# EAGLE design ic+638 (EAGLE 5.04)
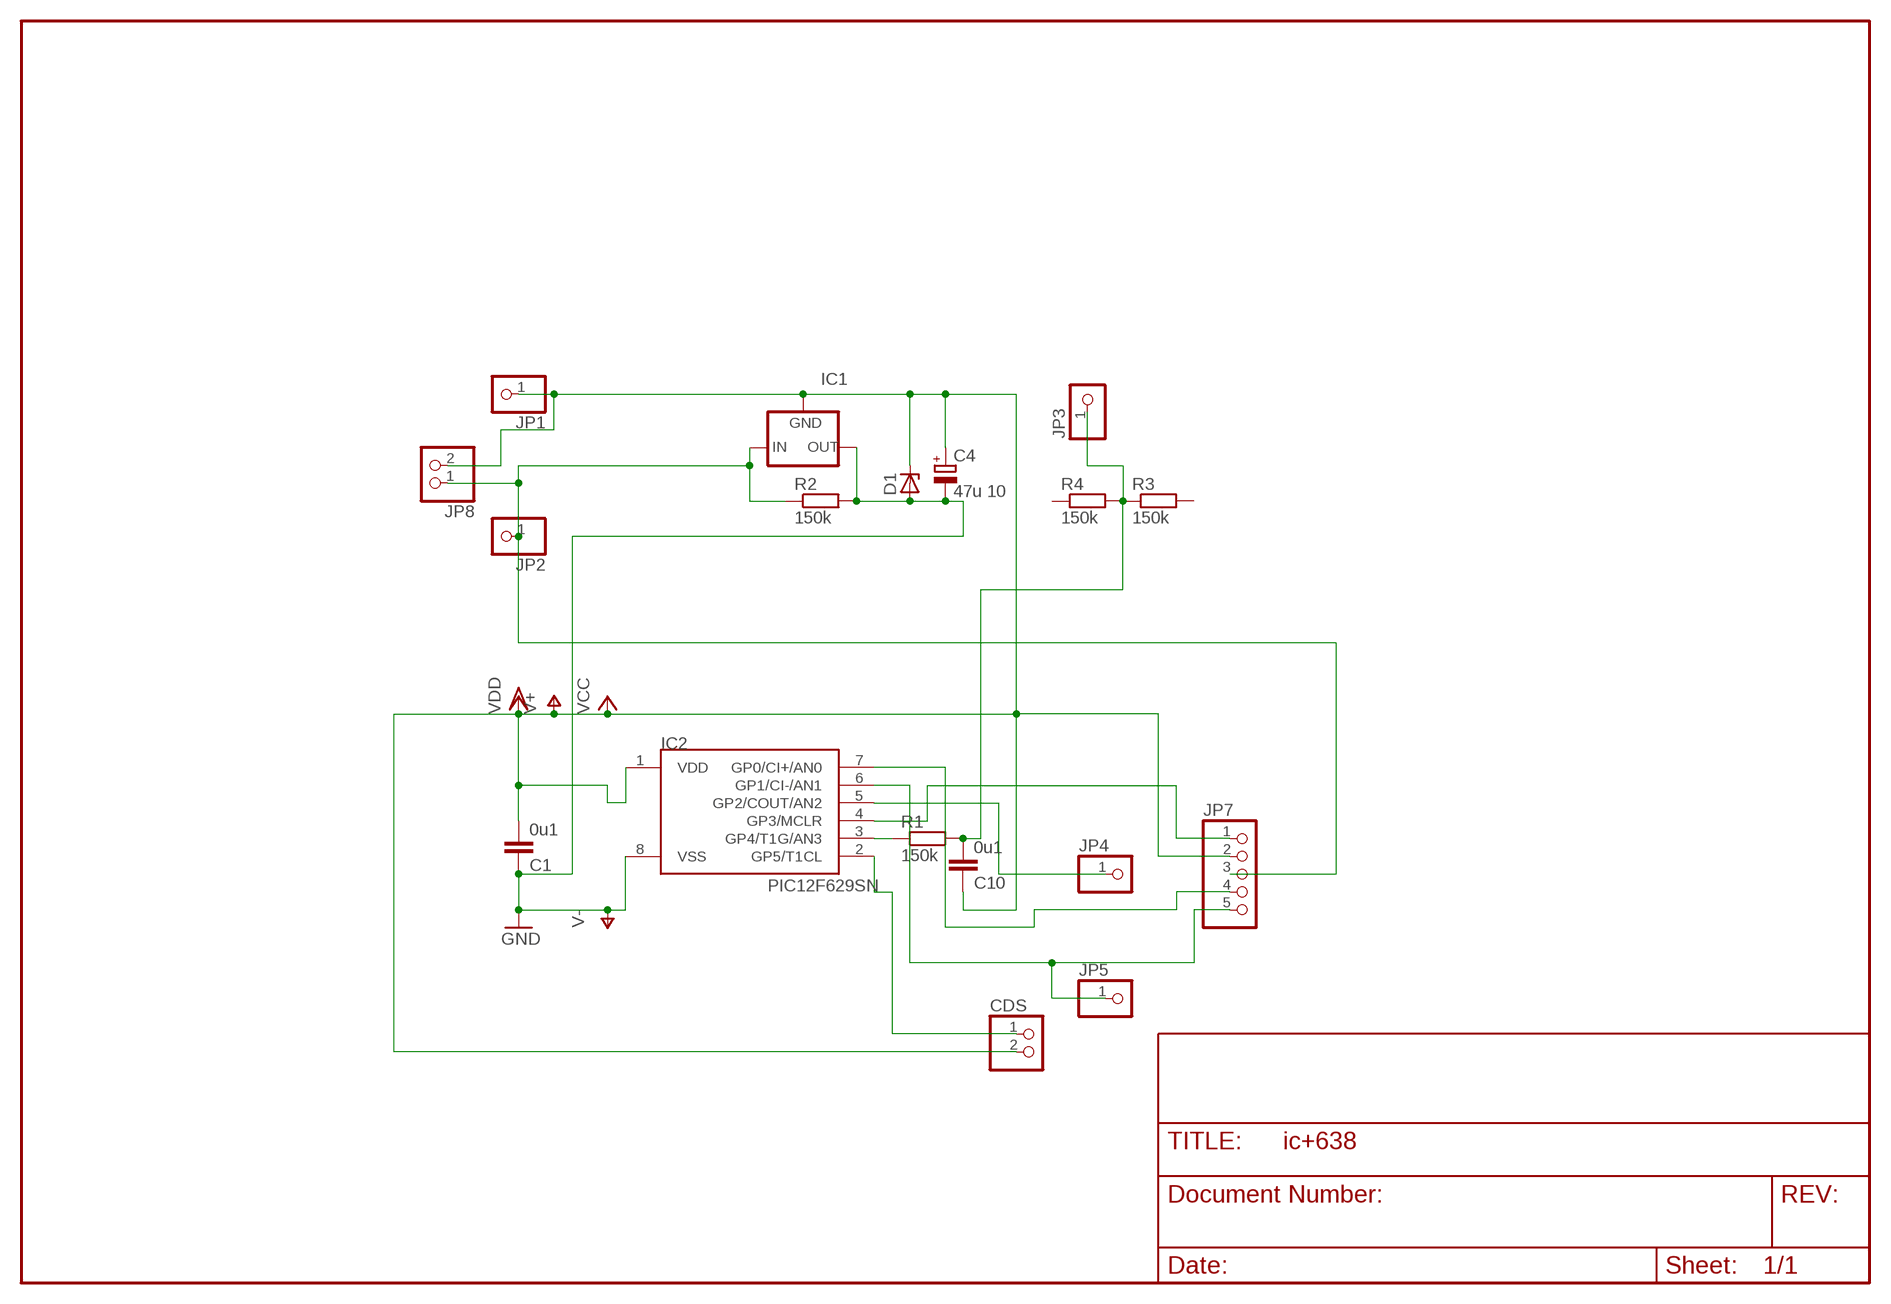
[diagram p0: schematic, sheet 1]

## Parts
C1  0u1  C-EUC1206  [C1206]
C4  47u 10  CPOL-EUE2.5-6  [E2,5-6]
C10  0u1  C-EUC1206  [C1206]
CDS  PINHD-1X2  [1X02]
D1  ZENER-DIODESOT23  [SOT23]
IC1  79LXX  [79LXX]
IC2  PIC12F629SN  [SO-08]
JP1  PINHD-1X1  [1X01]
JP2  PINHD-1X1  [1X01]
JP3  PINHD-1X1  [1X01]
JP4  PINHD-1X1  [1X01]
JP5  PINHD-1X1  [1X01]
JP7  PINHD-1X5  [1X05]
JP8  PINHD-1X2  [1X02]
R1  150k  R-EU_0204/2V  [0204V]
R2  150k  R-EU_0204/2V  [0204V]
R3  150k  R-EU_0204/2V  [0204V]
R4  150k  R-EU_0204/2V  [0204V]

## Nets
CDS: CDS.1 IC2.2(GP5/T1CL)
N$1: C10.2 JP3.1 R1.2 R3.1 R4.2
N$2: IC2.5(GP2/COUT/AN2) JP4.1
N$3: IC2.4(GP3/MCLR) JP7.1
N$8: IC2.3(GP4/T1G/AN3) R1.1
N$9: IC2.7(GP0/CI+/AN0) JP7.4
N$10: IC1.IN JP2.1 JP7.3 JP8.1 R2.1
N$15: IC2.6(GP1/CI-/AN1) JP5.1 JP7.5
V+: C1.2 C4.+ C10.1 CDS.2 D1.3(C) IC1.GND IC2.1(VDD) JP1.1 JP7.2 JP8.2 ; supply symbol labelled VCC, VDD
V-: C1.1 C4.- D1.1(A) IC1.OUT IC2.8(VSS) R2.2 ; supply symbol labelled GND
Unconnected: R3.2 R4.1

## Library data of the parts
C1 C10 = rcl:C-EU: CAPACITOR, European symbol
C4 = rcl:CPOL-EU: POLARIZED CAPACITOR, European symbol
CDS JP8 = pinhead:PINHD-1X2: PIN HEADER
D1 = diode-1:ZENER-DIODE: Z-Diode
IC1 = v-reg:79LXX: VOLTAGE REGULATOR
IC2 = microchip-3:PIC12F6*: uPC nW 1k Program Flash memory 2x Timer Comparator 10b A/D converter/ 4xIN
JP1-JP5 = pinhead:PINHD-1X1: PIN HEADER
JP7 = pinhead:PINHD-1X5: PIN HEADER
R1-R4 = rcl:R-EU_: RESISTOR, European symbol

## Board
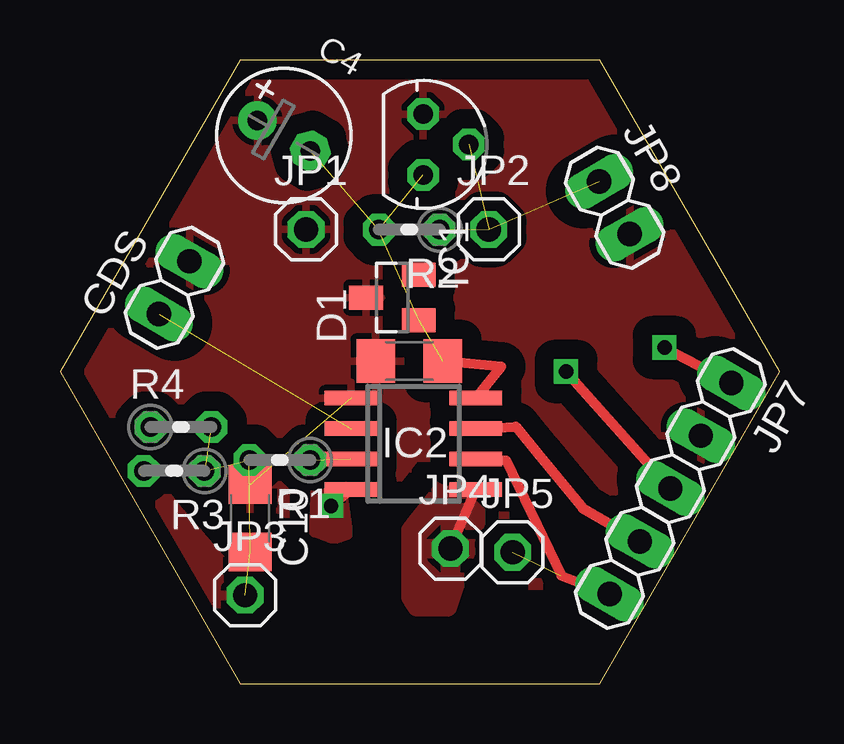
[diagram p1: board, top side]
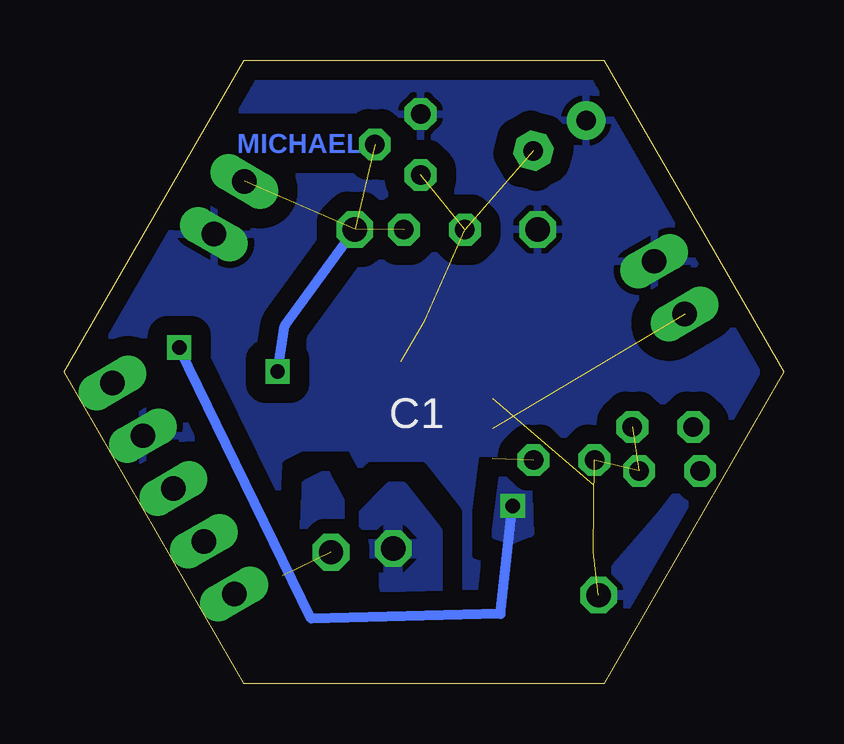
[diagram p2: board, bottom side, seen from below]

Size 30 x 25.98 mm. Coordinates in mm from the lower left corner, seen from the top.
Outline: 7.5,0 22.5,0 30,12.99 22.5,25.98 7.5,25.98 0,12.99 7.5,0
Copper layers (1*16): Top 0.035mm / dielectric 1.5mm / Bottom 0.035mm
Design rules "default *": minimum track width 10mil, minimum drill 24mil, track to track 8mil, track to pad 8mil, pad to pad 8mil, via to via 8mil, smd to smd 8mil, copper to edge 10mil, drill to drill 8mil, minimum pad ring 10mil, minimum via ring 8mil, stop-mask expansion 4mil, vias tented up to drill 0mil, thermal gap 10mil

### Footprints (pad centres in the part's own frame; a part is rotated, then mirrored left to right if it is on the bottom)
C1206 = smd 1.6 x 1.8: 1 -1.4,0; 2 1.4,0
E2,5-6 = drill 0.813 pad 1.6 round: + -1.27,0 | drill 0.813 pad 1.6 octagon: - 1.27,0
1X02 = drill 1.016 long: 1 -1.27,0; 2 1.27,0
SOT23 = smd 1 x 1.4: 1 -0.95,-1.1; 2 0.95,-1.1; 3 0,1.1
79LXX = drill 0.813 octagon: GND -1.27,0; IN 0,1.905; OUT 1.27,0
SO-08 = smd 0.6 x 2.2: 1 -1.905,-2.6; 2 -0.635,-2.6; 3 0.635,-2.6; 4 1.905,-2.6; 5 1.905,2.6; 6 0.635,2.6; 7 -0.635,2.6; 8 -1.905,2.6
1X01 = drill 1.016 octagon: 1 0,0
1X05 = drill 1.016 long: 1 -5.08,0; 2 -2.54,0; 3 0,0; 4 2.54,0; 5 5.08,0
0204V = drill 0.813 octagon: 1 -1.27,0; 2 1.27,0

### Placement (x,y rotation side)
C1  14.56,13.44 180 top
C4  9.34,22.83 330 top
C10  7.93,6.89 270 top
CDS  4.77,16.49 60 top
D1  13.86,16.08 90 top
IC1  15.14,22.46 270 top
IC2  14.74,9.99 270 top
JP1  10.26,18.92 0 top
JP2  17.88,18.92 0 top
JP3  7.72,3.68 0 top
JP4  16.28,5.62 0 top
JP5  18.87,5.47 0 top
JP7  25.45,8.13 240 top
JP8  23.12,19.82 300 top
R1  9.16,9.31 180 top
R2  14.56,18.91 180 top
R3  4.76,8.86 180 top
R4  5.04,10.69 0 top

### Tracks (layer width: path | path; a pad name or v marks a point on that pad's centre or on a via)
CDS  (1 unrouted)
N$1  (4 unrouted)
  pour Top (isolate 0.61): 2.1,10.8 7.2,2.1 6.9,4.9 5,7.1
  pour Bottom (isolate 0.61): 2.2,10.7 7.3,2 7,4.8 5.1,7
N$2
  Top 0.406: JP4.1 IC2.5
  pour Top (isolate 0.813): 16.15,3.21 14.88,3.21 14.63,3.59 14.63,6.38 16.03,8.16 16.28,8.16 17.42,7.02
  pour Bottom (isolate 0.813): 16.15,3.11 14.88,3.11 14.63,3.49 14.63,6.28 16.03,8.06 16.28,8.06 17.42,6.92
N$3  (via drill 0.6)
  Top 0.406: v25.2,14 JP7.1 | v11.3,7.4 IC2.4
  Bottom 0.406: v25.2,14 19.7,2.7 11.8,2.9 v11.3,7.4
  pour Top (isolate 0.61): 10.7,8.8 11.7,8.5 12,6.2 11.4,6 10.6,6.3
  pour Bottom (isolate 0.61): 10.7,8.8 11.7,8.5 12,6.2 11.4,6 10.6,6.3
N$5
  pour Top (isolate 0.61): 19.1,8.7 19.9,8.3 20.1,4.1 18.5,4.1 18.5,7.6
  pour Bottom (isolate 0.61): 19.1,8.7 19.9,8.3 20.1,4.1 18.5,4.1 18.5,7.6
N$8  (1 unrouted)
N$9
  Top 0.406: IC2.7 19,10.7 19.9,9.6 21.8,7.3 JP7.4
N$10  (via drill 0.6)  (3 unrouted)
  Top 0.406: JP7.3 v21.1,13
  Bottom 0.406: v21.1,13 20.8,14.9 JP2.1
N$15  (1 unrouted)
  Top 0.406: IC2.6 18.6,9.3 20.9,4.5 JP7.5
V+  (1 unrouted)
  pour Bottom (isolate 0.813, rank 4): 22.69,0.45 6.94,0.85 -0.63,14.71 7.44,25.75 23.4,26.48 24.95,23.34 29.84,13.01
  pour Top (isolate 0.813, rank 4): 22.85,25.64 30.02,13.23 22.99,0.25 7.24,0.65 -0.28,14.57 8.01,25.74
V-  (4 unrouted)
  Top 0.406: C1.1 18.4,13.2 IC2.8

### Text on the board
Bottom: MICHAELS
